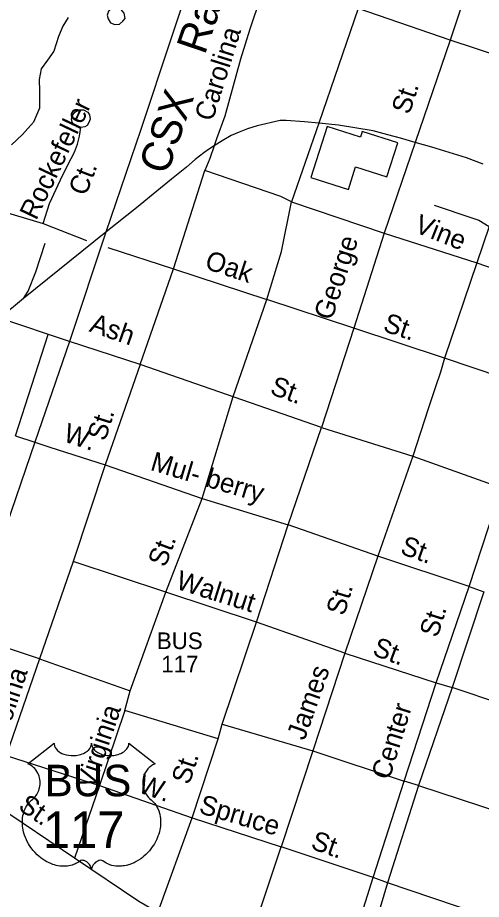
# Model space of a CAD drawing. Extents: x 2260773 to 2342389, y 552869 to 618546.
# Drawn here: x 2296824 to 2299105, y 594806 to 599147 of the extents above; entities that cross this region are included whole.
import ezdxf

# ---------------------------------------------------------------- set-up
doc = ezdxf.new("R2010")
doc.units = 0
for name, color, linetype in [('Exist Cultural Warehouse Building Footprint', 7, 'Continuous'), ('Exist Hydrographic Misc Water Feature', 7, 'Continuous'), ('Exist Railroad Mainline', 7, 'Continuous'), ('Exist Railroad Mainline Label', 7, 'Continuous'), ('Exist Railroad Siding', 7, 'Continuous'), ('Exist Road Non-System Type 51', 7, 'Continuous'), ('Exist Road Non-System Type 51 Label', 7, 'Continuous'), ('Exist Road Primary US Attributed', 7, 'Continuous'), ('Exist Road Primary US Label', 7, 'Continuous'), ('Exist Road Primary US Shield CELL', 7, 'Continuous'), ('Exist Road Primary US Shield Number Label', 7, 'Continuous'), ('Exist Road Secondary Type 51 Attributed', 7, 'Continuous'), ('Exist Road Secondary Type 51 Label', 7, 'Continuous')]:
    doc.layers.add(name, color=color, linetype=linetype)

msp = doc.modelspace()

# ---------------------------------------------------------------- linework, layer by layer
at = {"layer": 'Exist Cultural Warehouse Building Footprint'}
for p, q in [((2298346, 598610.3), (2298266.3, 598359.9)), ((2298510, 598558.1), (2298346, 598610.3)), ((2298518.9, 598586.2), (2298510, 598558.1)), ((2298693.7, 598530.5), (2298518.9, 598586.2)), ((2298640.3, 598362.8), (2298693.7, 598530.5)), ((2298450.8, 598301.2), (2298486, 598411.9)), ((2298486, 598411.9), (2298640.3, 598362.8)), ((2298266.3, 598359.9), (2298450.8, 598301.2))]:
    msp.add_line(p, q, dxfattribs=at)
at = {"layer": 'Exist Hydrographic Misc Water Feature'}
msp.add_lwpolyline([(2297073, 599147.6), (2297045.5, 599105.1), (2297024, 599053.2), (2297002.3, 598981.1), (2296971.1, 598936.7), (2296939.3, 598894.4), (2296929.9, 598842.3), (2296930.5, 598784.2), (2296930.9, 598700.6), (2296902.2, 598632), (2296848.3, 598571.9), (2296792.7, 598521.1)], dxfattribs=at)
at = {"layer": 'Exist Railroad Mainline'}
for p, q in [((2297256.9, 598090.6), (2296852.2, 597763.1)), ((2297256.9, 598090.6), (2297078.1, 597552.3)), ((2296852.2, 597763.1), (2296734, 597666.2))]:
    msp.add_line(p, q, dxfattribs=at)
for points in [[(2298059.6, 600259), (2298041.3, 600221.8), (2298023.6, 600191.5), (2297893.3, 599943.6), (2297846.2, 599839.4), (2297778.1, 599648.8), (2297729.5, 599498.3), (2297728.8, 599496.1), (2297430.1, 598596.1), (2297256.9, 598090.6)], [(2298779.1, 598532.2), (2298707, 598552.9), (2298644.9, 598570.2), (2298572.7, 598589.5), (2298402.5, 598617.6), (2298304.6, 598627), (2298234.4, 598633.8), (2298144.3, 598640.7), (2298115.3, 598640.5), (2298001.6, 598613.5), (2297953.7, 598599), (2297914, 598582.6), (2297874.1, 598566.3), (2297830.4, 598539.8), (2297790.8, 598515.8), (2297766.8, 598501.3), (2297739, 598481), (2297697.4, 598448.7), (2297653.8, 598410.2), (2297580.3, 598351.5), (2297508.9, 598293), (2297407.8, 598210.1), (2297256.9, 598090.6)], [(2299114.2, 598425.3), (2299032, 598456.4), (2298861.4, 598508.5), (2298779.1, 598532.2)], [(2297078.1, 597552.3), (2296908, 597056.4), (2296582, 596105.4), (2296419.8, 595632.1), (2296080.1, 594641.3), (2295988.2, 594369.4)]]:
    msp.add_lwpolyline(points, dxfattribs=at)
at = {"layer": 'Exist Railroad Siding'}
for points in [[(2298872.6, 598222.7), (2299063, 598158.8), (2299093.2, 598149.2), (2299142.8, 598118.2), (2299143.5, 598117.8), (2299179.9, 598084.1), (2299238.4, 598026.8), (2299311.5, 597931.6), (2299379.3, 597837.1), (2299388.4, 597824.5), (2299427.2, 597761), (2299453.8, 597707.3)], [(2296852.2, 597763.1), (2296875.9, 597799.2), (2296913, 597895.4), (2296959.7, 598035.8)]]:
    msp.add_lwpolyline(points, dxfattribs=at)
at = {"layer": 'Exist Road Non-System Type 51'}
for p, q in [((2298499.7, 599191.8), (2298304.6, 598627)), ((2298951.8, 599035.4), (2298499.7, 599191.8)), ((2299398.1, 598888.7), (2298951.8, 599035.4)), ((2298304.6, 598627), (2298170.7, 598239.3)), ((2297590.5, 597909.9), (2297744.1, 598394.5)), ((2298170.7, 598239.3), (2298626, 598086.3)), ((2296686.1, 598211.3), (2296948.7, 598133.8)), ((2296948.7, 598133.8), (2297163.2, 598048.6)), ((2299142.8, 598118.2), (2299083.3, 597938.7)), ((2298626, 598086.3), (2299083.3, 597938.7)), ((2297267.6, 598014.3), (2297590.5, 597909.9)), ((2299083.3, 597938.7), (2298923.7, 597469.7)), ((2299083.3, 597938.7), (2299379.3, 597837.1)), ((2297427, 597438.5), (2297590.5, 597909.9)), ((2297590.5, 597909.9), (2298049.6, 597758.2)), ((2297884.2, 597280.9), (2298049.6, 597758.2)), ((2298477, 597618.2), (2298049.6, 597758.2)), ((2296812.7, 597087), (2296973.9, 597586.3)), ((2298923.7, 597469.7), (2298477, 597618.2)), ((2299359.5, 597323.8), (2298923.7, 597469.7)), ((2297427, 597438.5), (2297253.6, 596945.5)), ((2297731.1, 596779.8), (2297884.2, 597280.9)), ((2296812.7, 597087), (2296908, 597056.4)), ((2296908, 597056.4), (2296982.5, 597032.5)), ((2296982.5, 597032.5), (2297253.6, 596945.5)), ((2298768.6, 596988.4), (2298595.2, 596494.6)), ((2297253.6, 596945.5), (2297096.3, 596468.7)), ((2297253.6, 596945.5), (2297731.1, 596779.8)), ((2299044.9, 596346), (2299203.8, 596832.4)), ((2297552.5, 596317.6), (2297731.1, 596779.8)), ((2297731.1, 596779.8), (2298153.8, 596649.8)), ((2298595.2, 596494.6), (2298153.8, 596649.8)), ((2297096.3, 596468.7), (2296931.2, 595990.4)), ((2297552.5, 596317.6), (2297096.3, 596468.7)), ((2298595.2, 596494.6), (2298433.2, 596017.8)), ((2299044.9, 596346), (2298595.2, 596494.6)), ((2298883.1, 595871.4), (2299044.9, 596346)), ((2299044.9, 596346), (2299117.2, 596319)), ((2297378.1, 595833), (2297552.5, 596317.6)), ((2297999.5, 596169.6), (2297552.5, 596317.6)), ((2299117.2, 596319), (2298960.7, 595849.2)), ((2298433.2, 596017.8), (2297999.5, 596169.6)), ((2296931.2, 595990.4), (2296698.6, 596067)), ((2296931.2, 595990.4), (2296767.7, 595513.6)), ((2296931.2, 595990.4), (2297378.1, 595833)), ((2298433.2, 596017.8), (2298275.8, 595537.6)), ((2298433.2, 596017.8), (2298883.1, 595871.4)), ((2298725.7, 595387.9), (2298883.1, 595871.4)), ((2298960.7, 595849.2), (2298795.7, 595366.8)), ((2298883.1, 595871.4), (2298960.7, 595849.2)), ((2299390.1, 595705.2), (2298960.7, 595849.2)), ((2297351.7, 595734.9), (2297378.1, 595833)), ((2297351.7, 595734.9), (2297227.1, 595365.6)), ((2297811, 595596.2), (2297351.7, 595734.9)), ((2297829.7, 595667.9), (2298275.8, 595537.6)), ((2296767.7, 595513.6), (2297227.1, 595365.6)), ((2298275.8, 595537.6), (2298120.7, 595064.1)), ((2298275.8, 595537.6), (2298725.7, 595387.9)), ((2298572.8, 594913.3), (2298725.7, 595387.9)), ((2298795.7, 595366.8), (2298725.7, 595387.9)), ((2297227.1, 595365.6), (2297103.7, 595007.7)), ((2297227.1, 595365.6), (2297681.8, 595206.7)), ((2298795.7, 595366.8), (2298643.7, 594886.7)), ((2298795.7, 595366.8), (2299232.5, 595221.8)), ((2297103.7, 595007.7), (2296694.4, 595284.3)), ((2297681.8, 595206.7), (2298120.7, 595064.1)), ((2297963.6, 594595.9), (2298120.7, 595064.1)), ((2298572.8, 594913.3), (2298120.7, 595064.1)), ((2298424.3, 594440.9), (2298572.8, 594913.3)), ((2298643.7, 594886.7), (2298572.8, 594913.3)), ((2298643.7, 594886.7), (2298501.5, 594414.7)), ((2299093.7, 594733.7), (2298643.7, 594886.7))]:
    msp.add_line(p, q, dxfattribs=at)
for points in [[(2298054.6, 599366.4), (2298018.8, 599248), (2297965.8, 599089.1), (2297920.7, 598942.6), (2297843.3, 598661.9), (2297802.4, 598549.5), (2297790.8, 598515.8)], [(2297332, 599188.8), (2297313.9, 599194.6), (2297291.9, 599194.4), (2297280, 599190.3), (2297270, 599178.3), (2297264.2, 599158.2), (2297268.4, 599140.3), (2297280.6, 599120.5), (2297302.6, 599112.6), (2297324.7, 599114.8), (2297340.5, 599128.9), (2297352.4, 599143), (2297348.2, 599169.1), (2297332, 599188.8)], [(2297134.2, 598605.3), (2297114.3, 598609.1), (2297100.1, 598619), (2297092, 598632.7), (2297087.9, 598648.8), (2297093.6, 598664.9), (2297105.5, 598680.8), (2297125.4, 598693), (2297147.4, 598693.4), (2297169.5, 598681.5), (2297177.6, 598667.6), (2297179.8, 598647.5), (2297173.9, 598629.7), (2297166.2, 598615.4), (2297154.1, 598609.5), (2297134.2, 598605.3)], [(2296948.7, 598133.8), (2296979.9, 598231.9), (2297034.6, 598348.4), (2297069.9, 598422.6), (2297103.3, 598484.9), (2297118.9, 598523.2), (2297128.5, 598563.2), (2297134.2, 598605.3)], [(2297790.8, 598515.8), (2297769.2, 598453.2), (2297744.1, 598394.5)], [(2298170.7, 598239.3), (2298118.4, 598266.6), (2297744.1, 598394.5)], [(2298049.6, 597758.2), (2298121.4, 597994.8), (2298170.7, 598239.3)], [(2298923.7, 597469.7), (2298903.8, 597400.9), (2298877.2, 597323.3), (2298844, 597221.3), (2298768.6, 596988.4)], [(2297513.6, 594740.8), (2297420.2, 594795.3), (2297103.7, 595007.7)]]:
    msp.add_lwpolyline(points, dxfattribs=at)
at = {"layer": 'Exist Road Primary US Attributed'}
for points in [[(2299100.3, 599483.4), (2298951.8, 599035.4), (2298779.1, 598532.2)], [(2298779.1, 598532.2), (2298626, 598086.3), (2298477, 597618.2), (2298318.4, 597128.8)], [(2297344.9, 594258.4), (2297513.6, 594740.8), (2297681.8, 595206.7), (2297811, 595596.2), (2297829.7, 595667.9), (2297999.5, 596169.6), (2298153.8, 596649.8), (2298318.4, 597128.8)], [(2298318.4, 597128.8), (2298768.6, 596988.4), (2299203.8, 596832.4)]]:
    msp.add_lwpolyline(points, dxfattribs=at)
at = {"layer": 'Exist Road Primary US Shield CELL'}
msp.add_lwpolyline([(2297002.9, 595574.5), (2297003.3, 595569.2), (2297004.6, 595562.9), (2297005.5, 595559.6), (2297008.5, 595553.4), (2297013.4, 595546), (2297020.2, 595538.8), (2297027.8, 595532.5), (2297033, 595529.2), (2297041.8, 595524.5), (2297051.7, 595520.3), (2297062.8, 595517.1), (2297074.1, 595514.8), (2297086.5, 595513.4), (2297098.7, 595513.2), (2297111.9, 595514.2), (2297126.5, 595517), (2297133.3, 595518.8), (2297140.8, 595521.3), (2297147.8, 595524.2), (2297155.5, 595528.3), (2297161.6, 595532.3), (2297166.4, 595535.8), (2297173.3, 595542.3), (2297178.7, 595549.1), (2297181, 595552.9), (2297183, 595556.5), (2297185.7, 595564.3), (2297186.4, 595567.7), (2297187, 595574.8), (2297187.4, 595568.8), (2297188, 595565.1), (2297189, 595561.5), (2297190.5, 595557.6), (2297193.2, 595552.1), (2297196.3, 595547.6), (2297202, 595540.8), (2297205.6, 595537.5), (2297208.9, 595534.8), (2297217.6, 595528.8), (2297227.8, 595523.6), (2297232.8, 595521.4), (2297238, 595519.6), (2297244.5, 595517.6), (2297251.3, 595516), (2297258, 595514.9), (2297264.8, 595513.9), (2297271.8, 595513.4), (2297277.5, 595513.2), (2297284.5, 595513.3), (2297290.9, 595513.7), (2297297.5, 595514.4), (2297304.8, 595515.6), (2297310.7, 595516.9), (2297318.4, 595519), (2297325.4, 595521.5), (2297331.5, 595524.2), (2297339.5, 595528.3), (2297346, 595532.4), (2297350.7, 595536.2), (2297356.3, 595541.3), (2297361.6, 595547.5), (2297364.7, 595552), (2297366.9, 595556.6), (2297369, 595561.5), (2297370.2, 595566.6), (2297370.9, 595571.1), (2297371, 595574.9), (2297499.6, 595472.5), (2297496.5, 595471.3), (2297489.6, 595467.9), (2297484, 595464.7), (2297475.2, 595458.4), (2297471.4, 595455), (2297467.6, 595451.4), (2297464.1, 595447.6), (2297461, 595444.1), (2297457.3, 595438.9), (2297453.9, 595433.7), (2297450.7, 595428), (2297448.3, 595423.1), (2297444.3, 595412.8), (2297442.4, 595406.2), (2297441.2, 595400.7), (2297439.7, 595389.2), (2297439.3, 595383.7), (2297439.3, 595378.3), (2297439.6, 595372.6), (2297440.2, 595367.2), (2297441.1, 595361.5), (2297442.1, 595356.5), (2297443.6, 595350.3), (2297445.9, 595343.2), (2297448.7, 595336.2), (2297454.6, 595325.1), (2297462.2, 595313.7), (2297467.6, 595307.3), (2297472.9, 595301.8), (2297480.8, 595295.1), (2297485.1, 595291.3), (2297490, 595286.4), (2297498.1, 595277), (2297501.4, 595272.6), (2297504.7, 595267.7), (2297507.7, 595262.6), (2297510.7, 595257.1), (2297513.2, 595252.4), (2297517.7, 595241.3), (2297521, 595230.6), (2297522.5, 595225), (2297524.9, 595212.4), (2297525.8, 595206.2), (2297526.8, 595193.8), (2297526.8, 595178.9), (2297525.7, 595164.8), (2297523, 595148.3), (2297520.8, 595138.4), (2297517.5, 595127), (2297514.2, 595117), (2297508.3, 595102.4), (2297503.1, 595091.7), (2297496.4, 595079.3), (2297491.7, 595071.7), (2297486.3, 595063.7), (2297479.6, 595054.4), (2297471.7, 595044.5), (2297462.2, 595034.1), (2297454.5, 595026.4), (2297444.5, 595017.5), (2297438.4, 595012.5), (2297429.7, 595005.9), (2297417.9, 594998), (2297406.2, 594991.3), (2297396.3, 594986.2), (2297387.4, 594982.4), (2297376.1, 594978), (2297357.1, 594972.8), (2297350.2, 594971.4), (2297342, 594970.1), (2297334.3, 594969.4), (2297326.8, 594968.9), (2297316.8, 594968.9), (2297306.9, 594969.7), (2297297.4, 594971), (2297287.7, 594973.1), (2297277.4, 594976.1), (2297268.1, 594979.8), (2297258.7, 594984.4), (2297242.8, 594994.5), (2297238.2, 594996.9), (2297235.6, 594997.6), (2297229.4, 594997.9), (2297223.7, 594996.7), (2297217.7, 594994.3), (2297214.2, 594992.4), (2297209.4, 594989.3), (2297205.8, 594986.4), (2297201.4, 594982.2), (2297198.3, 594978.7), (2297196, 594976), (2297191.5, 594968.9), (2297189.9, 594965.6), (2297188.3, 594961.2), (2297186.8, 594954.9), (2297184.8, 594962.9), (2297182.4, 594968.2), (2297179.7, 594972.8), (2297176.8, 594976.8), (2297172.4, 594982), (2297168.3, 594985.9), (2297163.5, 594989.8), (2297158.3, 594992.9), (2297154.2, 594995.1), (2297150.4, 594996.5), (2297145.7, 594997.6), (2297141.9, 594997.9), (2297138.8, 594997.9), (2297134.5, 594996.9), (2297128.7, 594992.7), (2297123.2, 594988.9), (2297117.2, 594985.2), (2297110.1, 594981.4), (2297104.8, 594978.9), (2297098.6, 594976.5), (2297091.3, 594974.1), (2297083.4, 594972), (2297075.3, 594970.4), (2297068.2, 594969.3), (2297060.5, 594968.6), (2297053.6, 594968.4), (2297046.4, 594968.5), (2297039.6, 594969), (2297031.8, 594969.7), (2297022.1, 594971.1), (2297014, 594972.9), (2297005.5, 594975.2), (2296996.8, 594978), (2296987.4, 594981.5), (2296975.7, 594986.6), (2296967.6, 594990.8), (2296954.8, 594998.2), (2296939.7, 595008.6), (2296928.4, 595017.8), (2296920.1, 595025.3), (2296907.8, 595037.8), (2296900.7, 595045.9), (2296889.4, 595060.5), (2296882.2, 595071), (2296877.5, 595078.8), (2296870.7, 595091.3), (2296866.9, 595099.1), (2296862, 595110.5), (2296858.2, 595120.9), (2296855, 595130.8), (2296853.3, 595137.1), (2296850.9, 595148.1), (2296849.4, 595155.9), (2296848, 595166.6), (2296847.2, 595178), (2296847, 595188.4), (2296847.3, 595197), (2296848.3, 595207.1), (2296850, 595217.9), (2296852, 595227), (2296853.9, 595233.7), (2296856.6, 595241.7), (2296860.2, 595250.6), (2296864.5, 595259.1), (2296868.5, 595266.2), (2296873.6, 595273.8), (2296878.6, 595280.2), (2296885.2, 595287.4), (2296892, 595293.9), (2296898.3, 595299), (2296905.8, 595306.3), (2296909.6, 595310.7), (2296914.3, 595316.9), (2296918, 595322.6), (2296921, 595327.7), (2296924.9, 595335.2), (2296927.3, 595340.8), (2296930.2, 595349.5), (2296931.7, 595355.5), (2296933.2, 595363.4), (2296934.2, 595370.7), (2296934.6, 595379.9), (2296934.4, 595387.5), (2296933.4, 595396.4), (2296931.7, 595404.9), (2296929.7, 595412.4), (2296926.5, 595420.9), (2296923.6, 595427.1), (2296918.6, 595435.6), (2296913.2, 595443.4), (2296907.5, 595449.8), (2296901.8, 595455.5), (2296896.3, 595459.7), (2296891.1, 595463.4), (2296884.6, 595467.4), (2296878.3, 595470.5), (2296874.3, 595472.1)], close=True, dxfattribs=at)
at = {"layer": 'Exist Road Secondary Type 51 Attributed'}
for points in [[(2297078.1, 597552.3), (2296734, 597666.2)], [(2298318.4, 597128.8), (2297427, 597438.5), (2297078.1, 597552.3)]]:
    msp.add_lwpolyline(points, dxfattribs=at)

# ---------------------------------------------------------------- texts
at = {"layer": 'Exist Railroad Mainline Label'}
for s, rotation, p in [('Railroad', 71.1618, (2297744.2, 598959.2)), ('CSX', 70.9338, (2297558.7, 598367.5))]:
    msp.add_text(s, height=150, rotation=rotation, dxfattribs=at).set_placement(p)
at = {"layer": 'Exist Road Non-System Type 51 Label'}
for s, rotation, p in [('Carolina', 72.5588, (2297782.2, 598631.6)), ('Rockefeller', 64.5584, (2296915, 598145.2)), ('Ct.', 68.983, (2297159.3, 598264.6)), ('Vine', 338.359, (2298770.2, 598093)), ('Oak', 341.7149, (2297739.2, 597912.6)), ('St.', 341.4928, (2298616.1, 597604.8)), ('St.', 72.4403, (2297254.8, 597057.4)), ('W.', 341.5766, (2297043.1, 597062.1)), ('Mul- berry', 343.4619, (2297471.6, 596920.5)), ('St.', 340.2035, (2298700.8, 596508.9)), ('St.', 69.1292, (2297550.3, 596436.2)), ('Walnut', 342.5615, (2297597.2, 596336.2)), ('St.', 73.303, (2298430.3, 596197.9)), ('St.', 72.3346, (2298888.8, 596090.3)), ('St.', 339.4269, (2298564, 596010)), ('Carolina', 71.7381, (2296726.3, 595478.9)), ('James', 70.474, (2298235.1, 595584.3)), ('Center', 72.8763, (2298652.2, 595389.5)), ('Virginia', 71.3786, (2297198.7, 595343.4)), ('W.', 341.1148, (2297410.7, 595334.5)), ('St.', 325.6048, (2296821.4, 595251.6)), ('Spruce', 343.5681, (2297710.7, 595231.8)), ('St.', 340.6683, (2298260.7, 595056.4))]:
    msp.add_text(s, height=95, rotation=rotation, dxfattribs=at).set_placement(p)
at = {"layer": 'Exist Road Primary US Label'}
for s, rotation, p in [('St.', 71.5632, (2298750.4, 598665.3)), ('George', 71.8676, (2298368.9, 597652.1)), ('St.', 71.7468, (2297668.1, 595366.1))]:
    msp.add_text(s, height=95, rotation=rotation, dxfattribs=at).set_placement(p)
for s, p in [('BUS', (2297508.6, 596037.9)), ('117', (2297530.2, 595923))]:
    msp.add_text(s, height=82.02, dxfattribs=at).set_placement(p)
at = {"layer": 'Exist Road Primary US Shield Number Label'}
for s, height, p in [('BUS', 155, (2296956.6, 595313.2)), ('117', 180, (2296947.7, 595058.4))]:
    msp.add_text(s, height=height, dxfattribs=at).set_placement(p)
at = {"layer": 'Exist Road Secondary Type 51 Label'}
for s, rotation, p in [('Ash', 340.9807, (2297171.9, 597603.1)), ('St.', 340.0632, (2298060.2, 597295.2))]:
    msp.add_text(s, height=95, rotation=rotation, dxfattribs=at).set_placement(p)

doc.saveas('drawing.dxf')
